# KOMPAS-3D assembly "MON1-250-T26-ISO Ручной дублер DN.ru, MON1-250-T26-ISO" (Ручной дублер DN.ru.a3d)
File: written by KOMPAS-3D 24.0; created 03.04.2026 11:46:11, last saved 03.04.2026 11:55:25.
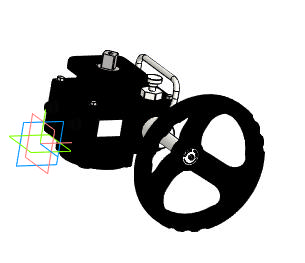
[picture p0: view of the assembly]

Document properties: Автор: R2D2; Полное имя файла: E:\Работа\Зайцев\Аксессуары для пневмоприводов\Ручной дублер DN.ru\MON1-250-T26-ISO Ручной дублер DN.ru\исходные материалы\MON1-250-T26-ISO Ручной дублер DN.ru.a3d

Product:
- Component [detail]: Деталь1  | qty 1  | pos. 1  | Масса: 5.630796; Автор: R2D2; source file: Деталь1 Деталь1.m3d
- Component [detail]: Деталь 2  | qty 1  | pos. 2  | Масса: 1.093853; Автор: R2D2; source file: Деталь 2 Деталь 2.m3d
- Component [detail]: AS 1427 - M5 x 10(4)  | designation AS 1427 - M5 x 10  | qty 1  | pos. 3  | Масса: 0.003197; Автор: R2D2; source file: AS 1427 - M5 x 10 AS 1427 - M5 x 10(4).m3d
- Component [detail]: AS 1427 - M5 x 10(4)  | designation AS 1427 - M5 x 10  | qty 3  | pos. 3  | Масса: 0.003197; Комментарий: Винты мелкие крепежные   метрические ISO; Автор: R2D2; additional columns: Сталь, мягкая; source file: AS 1427 - M5 x 10 AS 1427 - M5 x 10(4).m3d
- Component [detail]: AS 1420 - 1973 - M3 x 6  | qty 1  | pos. 4  | Масса: 0.000819; Автор: R2D2; source file: AS 1420 - 1973 - M3 x 6 AS 1420 - 1973 - M3 x 6.m3d
- Part/product: MON1-250-T26-ISO Ручной дублер DN.ru  | designation MON1-250-T26-ISO
    Масса: 3
    Раздел спецификации: Прочие изделия
    Примечание: D290-00336

Referenced files in E:\Работа\Зайцев\Аксессуары для пневмоприводов\Ручной дублер DN.ru\MON1-250-T26-ISO Ручной дублер DN.ru\исходные материалы\: Деталь1 Деталь1.m3d, Деталь 2 Деталь 2.m3d, AS 1427 - M5 x 10 AS 1427 - M5 x 10(4).m3d, AS 1420 - 1973 - M3 x 6 AS 1420 - 1973 - M3 x 6.m3d
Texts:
  Программные изделия  и базы данных
  AS 1427 - M5 x 10
  MON1-250-T26-ISO
  Деталь1 Деталь1
  Деталь 2 Деталь 2
  AS 1427 - M5 x 10 AS 1427 - M5 x 10(4) (1)
  AS 1427 - M5 x 10 AS 1427 - M5 x 10(4) (2)
  AS 1427 - M5 x 10 AS 1427 - M5 x 10(4) (3)
  AS 1427 - M5 x 10 AS 1427 - M5 x 10(4) (4)
  AS 1420 - 1973 - M3 x 6 AS 1420 - 1973 - M3 x 6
